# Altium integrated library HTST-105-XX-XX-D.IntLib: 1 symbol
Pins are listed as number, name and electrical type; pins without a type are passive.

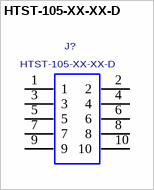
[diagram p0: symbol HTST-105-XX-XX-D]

## HTST-105-XX-XX-D
designator J?
HIGH TEMP TOP SHROUD TERMINAL STRIP.; MANUFACTURER: SAMTEC
footprint HTST-105-XX-XX-D
pins: 1, 2, 3, 4, 5, 6, 7, 8, 9, 10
